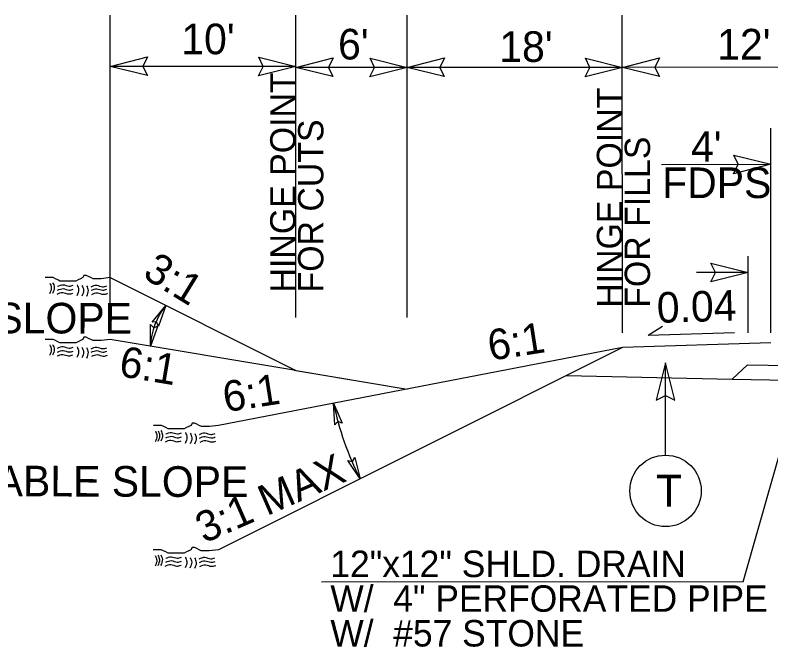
# Model space of a CAD drawing. Extents: x 2241081 to 2251104, y 658534 to 663427.
# Drawn here: x 2243852 to 2244055.6, y 661311.7 to 661481.9 of the extents above; entities that cross this region are included whole.
import ezdxf

# ---------------------------------------------------------------- set-up
doc = ezdxf.new("R2010")
doc.units = 0
for name, color, linetype in [('Old_Level_1', 7, 'Continuous'), ('Old_Level_2', 7, 'Continuous'), ('Old_Level_3', 7, 'Continuous'), ('Prop Dimension', 7, 'Continuous'), ('Prop Dimension Text', 7, 'Continuous'), ('Prop PHM Text', 7, 'Continuous'), ('Typical Arrow Superelevation CELL', 7, 'Continuous'), ('Typical Berm Information CELL', 7, 'Continuous'), ('Typical Hinge Slope Interstate CELL', 7, 'Continuous'), ('Typical ID Circle CELL', 7, 'Continuous'), ('Typical Terminator CELL', 7, 'Continuous'), ('Typical Text ID Circle CELL', 7, 'Continuous')]:
    doc.layers.add(name, color=color, linetype=linetype)

# ---------------------------------------------------------------- blocks, each defined once
blk = doc.blocks.new('TERMINATOR')
at = {"layer": 'Typical Terminator CELL'}
blk.add_lwpolyline([(-0.4687, 0.0807), (0, 0), (-0.4713, -0.0833), (-0.4114, 0)], close=True, dxfattribs=at)

msp = doc.modelspace()

# ---------------------------------------------------------------- linework, layer by layer
at = {"layer": 'Old_Level_1'}
for p, q in [((2243877.64, 661411.14), (2243927.64, 661386.14)), ((2243927.64, 661386.14), (2243877.64, 661394.48)), ((2244015.65, 661392.31), (2243906.82, 661371.36)), ((2243927.64, 661386.14), (2243949.64, 661382.48))]:
    msp.add_line(p, q, dxfattribs=at)
for points in [[(2243877.64, 661411.14), (2243875.17, 661410.84), (2243874.56, 661410.84), (2243873.63, 661410.84), (2243873.01, 661410.84), (2243872.4, 661411.15), (2243871.78, 661411.45), (2243871.17, 661411.76), (2243870.55, 661411.76), (2243870.24, 661411.15), (2243869.62, 661410.84), (2243869.01, 661410.53), (2243868.39, 661410.22), (2243867.78, 661410.22), (2243867.16, 661410.22), (2243866.54, 661410.22), (2243865.93, 661410.22), (2243865.31, 661410.22), (2243864.7, 661410.22), (2243864.08, 661410.22), (2243863.46, 661410.53), (2243862.85, 661410.84), (2243862.23, 661411.15), (2243861.31, 661411.15), (2243860.69, 661411.15), (2243860.07, 661411.15)], [(2243877.64, 661394.48), (2243875.17, 661394.17), (2243874.56, 661394.17), (2243873.63, 661394.17), (2243873.01, 661394.17), (2243872.4, 661394.48), (2243871.78, 661394.79), (2243871.17, 661395.1), (2243870.55, 661395.1), (2243870.24, 661394.48), (2243869.62, 661394.17), (2243869.01, 661393.86), (2243868.39, 661393.56), (2243867.78, 661393.56), (2243867.16, 661393.56), (2243866.54, 661393.56), (2243865.93, 661393.56), (2243865.31, 661393.56), (2243864.7, 661393.56), (2243864.08, 661393.56), (2243863.46, 661393.86), (2243862.85, 661394.17), (2243862.23, 661394.48), (2243861.31, 661394.48), (2243860.69, 661394.48), (2243860.07, 661394.48)], [(2243906.82, 661371.36), (2243904.35, 661371.06), (2243903.73, 661371.06), (2243902.81, 661371.06), (2243902.19, 661371.06), (2243901.58, 661371.36), (2243900.96, 661371.67), (2243900.34, 661371.98), (2243899.73, 661371.98), (2243899.42, 661371.36), (2243898.8, 661371.06), (2243898.19, 661370.75), (2243897.57, 661370.44), (2243896.95, 661370.44), (2243896.34, 661370.44), (2243895.72, 661370.44), (2243895.11, 661370.44), (2243894.49, 661370.44), (2243893.87, 661370.44), (2243893.26, 661370.44), (2243892.64, 661370.75), (2243892.03, 661371.06), (2243891.41, 661371.36), (2243890.48, 661371.36), (2243889.87, 661371.36), (2243889.25, 661371.36)], [(2243906.77, 661337.87), (2243904.31, 661337.57), (2243903.69, 661337.57), (2243902.77, 661337.57), (2243902.15, 661337.57), (2243901.54, 661337.87), (2243900.92, 661338.18), (2243900.3, 661338.49), (2243899.69, 661338.49), (2243899.38, 661337.87), (2243898.76, 661337.57), (2243898.15, 661337.26), (2243897.53, 661336.95), (2243896.91, 661336.95), (2243896.3, 661336.95), (2243895.68, 661336.95), (2243895.07, 661336.95), (2243894.45, 661336.95), (2243893.83, 661336.95), (2243893.22, 661336.95), (2243892.6, 661337.26), (2243891.98, 661337.57), (2243891.37, 661337.87), (2243890.44, 661337.87), (2243889.83, 661337.87), (2243889.21, 661337.87)]]:
    msp.add_lwpolyline(points, dxfattribs=at)
for points in [[(2243861.33, 661409.7), (2243861.75, 661408.45), (2243861.29, 661406.81)], [(2243861.33, 661409.7), (2243861.75, 661408.45), (2243861.29, 661406.81)], [(2243862.11, 661409.78), (2243862.53, 661408.54), (2243862.08, 661406.89)], [(2243862.11, 661409.78), (2243862.53, 661408.54), (2243862.08, 661406.89)], [(2243863.44, 661408.81), (2243864.93, 661409.24), (2243866.53, 661408.84), (2243867.67, 661409.1)], [(2243863.44, 661408.81), (2243864.93, 661409.24), (2243866.53, 661408.84), (2243867.67, 661409.1)], [(2243868.69, 661409.17), (2243869.11, 661407.93), (2243868.66, 661406.28)], [(2243868.69, 661409.17), (2243869.11, 661407.93), (2243868.66, 661406.28)], [(2243870.01, 661409.07), (2243870.43, 661407.82), (2243869.98, 661406.17)], [(2243870.01, 661409.07), (2243870.43, 661407.82), (2243869.98, 661406.17)], [(2243872.46, 661408.67), (2243873.97, 661409.1), (2243875.55, 661408.69), (2243876.7, 661408.95)], [(2243872.46, 661408.67), (2243873.97, 661409.1), (2243875.55, 661408.69), (2243876.7, 661408.95)], [(2243863.31, 661406.71), (2243864.81, 661407.13), (2243866.41, 661406.74), (2243867.55, 661406.99)], [(2243863.31, 661406.71), (2243864.81, 661407.13), (2243866.41, 661406.74), (2243867.55, 661406.99)], [(2243863.43, 661407.77), (2243864.93, 661408.19), (2243866.52, 661407.79), (2243867.66, 661408.04)], [(2243863.43, 661407.77), (2243864.93, 661408.19), (2243866.52, 661407.79), (2243867.66, 661408.04)], [(2243871.22, 661408.96), (2243871.64, 661407.71), (2243871.19, 661406.07)], [(2243871.22, 661408.96), (2243871.64, 661407.71), (2243871.19, 661406.07)], [(2243872.5, 661407.73), (2243874.01, 661408.16), (2243875.59, 661407.75), (2243876.74, 661408.01)], [(2243872.5, 661407.73), (2243874.01, 661408.16), (2243875.59, 661407.75), (2243876.74, 661408.01)], [(2243872.66, 661406.63), (2243874.16, 661407.06), (2243875.75, 661406.66), (2243876.9, 661406.92)], [(2243872.66, 661406.63), (2243874.16, 661407.06), (2243875.75, 661406.66), (2243876.9, 661406.92)], [(2243861.33, 661393.03), (2243861.75, 661391.79), (2243861.29, 661390.14)], [(2243861.33, 661393.03), (2243861.75, 661391.79), (2243861.29, 661390.14)], [(2243862.11, 661393.12), (2243862.53, 661391.87), (2243862.08, 661390.23)], [(2243862.11, 661393.12), (2243862.53, 661391.87), (2243862.08, 661390.23)], [(2243863.43, 661391.1), (2243864.93, 661391.53), (2243866.52, 661391.12), (2243867.66, 661391.38)], [(2243863.43, 661391.1), (2243864.93, 661391.53), (2243866.52, 661391.12), (2243867.66, 661391.38)], [(2243863.44, 661392.15), (2243864.93, 661392.58), (2243866.53, 661392.17), (2243867.67, 661392.43)], [(2243863.44, 661392.15), (2243864.93, 661392.58), (2243866.53, 661392.17), (2243867.67, 661392.43)], [(2243868.69, 661392.5), (2243869.11, 661391.26), (2243868.66, 661389.61)], [(2243868.69, 661392.5), (2243869.11, 661391.26), (2243868.66, 661389.61)], [(2243870.01, 661392.4), (2243870.43, 661391.16), (2243869.98, 661389.51)], [(2243870.01, 661392.4), (2243870.43, 661391.16), (2243869.98, 661389.51)], [(2243871.22, 661392.29), (2243871.64, 661391.05), (2243871.19, 661389.4)], [(2243871.22, 661392.29), (2243871.64, 661391.05), (2243871.19, 661389.4)], [(2243872.46, 661392.01), (2243873.97, 661392.43), (2243875.55, 661392.03), (2243876.7, 661392.28)], [(2243872.46, 661392.01), (2243873.97, 661392.43), (2243875.55, 661392.03), (2243876.7, 661392.28)], [(2243872.5, 661391.06), (2243874.01, 661391.49), (2243875.59, 661391.08), (2243876.74, 661391.34)], [(2243872.5, 661391.06), (2243874.01, 661391.49), (2243875.59, 661391.08), (2243876.74, 661391.34)], [(2243863.31, 661390.04), (2243864.81, 661390.47), (2243866.41, 661390.07), (2243867.55, 661390.33)], [(2243863.31, 661390.04), (2243864.81, 661390.47), (2243866.41, 661390.07), (2243867.55, 661390.33)], [(2243872.66, 661389.97), (2243874.16, 661390.4), (2243875.75, 661389.99), (2243876.9, 661390.25)], [(2243872.66, 661389.97), (2243874.16, 661390.4), (2243875.75, 661389.99), (2243876.9, 661390.25)]]:
    msp.add_spline(points, degree=3, dxfattribs=at)
at = {"layer": 'Old_Level_2'}
for p, q in [((2244055.65, 661393.61), (2244015.65, 661392.31)), ((2244049.3, 661387.7), (2244045.15, 661383.83)), ((2244049.3, 661387.7), (2244075.64, 661387.13)), ((2244000.6, 661384.78), (2244045.15, 661383.83)), ((2244045.15, 661383.83), (2244075.64, 661383.18))]:
    msp.add_line(p, q, dxfattribs=at)
for points in [[(2243889.78, 661369.78), (2243890.2, 661368.54), (2243889.74, 661366.89)], [(2243889.78, 661369.78), (2243890.2, 661368.54), (2243889.74, 661366.89)], [(2243890.51, 661369.92), (2243890.93, 661368.67), (2243890.47, 661367.02)], [(2243890.51, 661369.92), (2243890.93, 661368.67), (2243890.47, 661367.02)], [(2243891.28, 661370), (2243891.71, 661368.76), (2243891.26, 661367.11)], [(2243891.28, 661370), (2243891.71, 661368.76), (2243891.26, 661367.11)], [(2243892.61, 661369.03), (2243894.11, 661369.46), (2243895.71, 661369.06), (2243896.85, 661369.32)], [(2243892.61, 661369.03), (2243894.11, 661369.46), (2243895.71, 661369.06), (2243896.85, 661369.32)], [(2243892.61, 661367.98), (2243894.11, 661368.41), (2243895.7, 661368), (2243896.84, 661368.26)], [(2243892.61, 661367.98), (2243894.11, 661368.41), (2243895.7, 661368), (2243896.84, 661368.26)], [(2243897.87, 661369.39), (2243898.29, 661368.15), (2243897.84, 661366.5)], [(2243897.87, 661369.39), (2243898.29, 661368.15), (2243897.84, 661366.5)], [(2243899.18, 661369.28), (2243899.61, 661368.04), (2243899.16, 661366.39)], [(2243899.18, 661369.28), (2243899.61, 661368.04), (2243899.16, 661366.39)], [(2243900.4, 661369.18), (2243900.82, 661367.93), (2243900.36, 661366.29)], [(2243900.4, 661369.18), (2243900.82, 661367.93), (2243900.36, 661366.29)], [(2243901.64, 661368.89), (2243903.15, 661369.32), (2243904.73, 661368.91), (2243905.88, 661369.17)], [(2243901.64, 661368.89), (2243903.15, 661369.32), (2243904.73, 661368.91), (2243905.88, 661369.17)], [(2243901.68, 661367.94), (2243903.19, 661368.38), (2243904.77, 661367.97), (2243905.92, 661368.23)], [(2243901.68, 661367.94), (2243903.19, 661368.38), (2243904.77, 661367.97), (2243905.92, 661368.23)], [(2243892.49, 661366.93), (2243893.99, 661367.35), (2243895.59, 661366.96), (2243896.73, 661367.21)], [(2243892.49, 661366.93), (2243893.99, 661367.35), (2243895.59, 661366.96), (2243896.73, 661367.21)], [(2243901.84, 661366.85), (2243903.34, 661367.28), (2243904.93, 661366.88), (2243906.08, 661367.14)], [(2243889.74, 661336.28), (2243890.16, 661335.04), (2243889.7, 661333.4)], [(2243889.74, 661336.28), (2243890.16, 661335.04), (2243889.7, 661333.4)], [(2243890.47, 661336.43), (2243890.88, 661335.18), (2243890.43, 661333.53)], [(2243890.47, 661336.43), (2243890.88, 661335.18), (2243890.43, 661333.53)], [(2243891.24, 661336.51), (2243891.67, 661335.26), (2243891.21, 661333.62)], [(2243891.24, 661336.51), (2243891.67, 661335.26), (2243891.21, 661333.62)], [(2243892.57, 661335.54), (2243894.07, 661335.97), (2243895.67, 661335.57), (2243896.81, 661335.82)], [(2243892.57, 661335.54), (2243894.07, 661335.97), (2243895.67, 661335.57), (2243896.81, 661335.82)], [(2243897.83, 661335.89), (2243898.25, 661334.65), (2243897.8, 661333.01)], [(2243897.83, 661335.89), (2243898.25, 661334.65), (2243897.8, 661333.01)], [(2243899.14, 661335.79), (2243899.57, 661334.55), (2243899.11, 661332.9)], [(2243899.14, 661335.79), (2243899.57, 661334.55), (2243899.11, 661332.9)], [(2243900.36, 661335.68), (2243900.78, 661334.44), (2243900.32, 661332.8)], [(2243900.36, 661335.68), (2243900.78, 661334.44), (2243900.32, 661332.8)], [(2243901.6, 661335.4), (2243903.11, 661335.83), (2243904.69, 661335.42), (2243905.84, 661335.67)], [(2243901.6, 661335.4), (2243903.11, 661335.83), (2243904.69, 661335.42), (2243905.84, 661335.67)], [(2243892.45, 661333.44), (2243893.95, 661333.86), (2243895.55, 661333.46), (2243896.69, 661333.72)], [(2243892.45, 661333.44), (2243893.95, 661333.86), (2243895.55, 661333.46), (2243896.69, 661333.72)], [(2243892.56, 661334.49), (2243894.07, 661334.92), (2243895.66, 661334.51), (2243896.8, 661334.77)], [(2243892.56, 661334.49), (2243894.07, 661334.92), (2243895.66, 661334.51), (2243896.8, 661334.77)], [(2243901.64, 661334.45), (2243903.15, 661334.89), (2243904.73, 661334.48), (2243905.88, 661334.73)], [(2243901.64, 661334.45), (2243903.15, 661334.89), (2243904.73, 661334.48), (2243905.88, 661334.73)], [(2243901.79, 661333.36), (2243903.3, 661333.79), (2243904.89, 661333.39), (2243906.03, 661333.64)]]:
    msp.add_spline(points, degree=3, dxfattribs=at)
at = {"layer": 'Prop Dimension'}
for centre, radius, start, end in [((2243907.58, 661391.82), 19.12, 141.6676, 177.4305), ((2244017.16, 661393.77), 81.05, 191.6788, 206.9901)]:
    msp.add_arc(centre, radius, start, end, dxfattribs=at)
at = {"layer": 'Prop Dimension Text'}
for p, q in [((2243877.63, 661400.38), (2243877.63, 661481.85)), ((2243927.63, 661400.38), (2243927.63, 661481.85)), ((2243957.63, 661400.38), (2243957.63, 661481.85)), ((2244015.64, 661396.26), (2244015.59, 661481.85)), ((2243877.63, 661468.17), (2243877.63, 661468.17)), ((2243927.63, 661468.04), (2243877.63, 661468.04)), ((2243927.63, 661468.17), (2243927.63, 661468.17)), ((2243957.63, 661467.78), (2243927.63, 661467.78)), ((2244015.65, 661467.78), (2243957.63, 661467.78)), ((2244075.6, 661467.82), (2244015.6, 661467.78)), ((2244055.64, 661396.29), (2244055.61, 661451.37)), ((2244026.17, 661441.66), (2244055.62, 661441.68)), ((2244049.46, 661396.29), (2244049.46, 661416.95)), ((2244049.46, 661412.56), (2244035.59, 661412.55)), ((2244048.2, 661329.21), (2244060.85, 661373.9)), ((2244048.2, 661329.21), (2243934.53, 661329.14))]:
    msp.add_line(p, q, dxfattribs=at)
at = {"layer": 'Typical Arrow Superelevation CELL'}
for q in [(2244026.44, 661398.06), (2244045.85, 661396.35)]:
    msp.add_line((2244022.55, 661395.65), q, dxfattribs=at)
at = {"layer": 'Typical Hinge Slope Interstate CELL'}
for p, q in [((2244015.65, 661392.31), (2243906.77, 661337.87)), ((2243927.14, 661386.23), (2243957.64, 661381.14))]:
    msp.add_line(p, q, dxfattribs=at)
at = {"layer": 'Typical ID Circle CELL'}
msp.add_line((2244027.24, 661363.31), (2244027.24, 661388.17), dxfattribs=at)
msp.add_circle((2244027.24, 661353.7), 9.62, dxfattribs=at)
at = {"layer": 'Typical Terminator CELL'}
for points in [[(2243888.92, 661399.11), (2243892.58, 661403.67), (2243890.67, 661398.1), (2243890.13, 661399.24)], [(2243890.47, 661398.17), (2243888.48, 661392.67), (2243888.49, 661398.56), (2243889.37, 661397.66)], [(2243938.18, 661371.52), (2243937.78, 661377.36), (2243940.15, 661371.96), (2243938.98, 661372.44)], [(2243943.52, 661362.66), (2243944.93, 661356.98), (2243941.66, 661361.88), (2243942.9, 661361.62)]]:
    msp.add_lwpolyline(points, close=True, dxfattribs=at)

# ---------------------------------------------------------------- block references
for p, xscale, yscale, rotation in [((2243877.63, 661468.04), 21.314641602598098, 30.593161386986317, -179.96511250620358), ((2243927.63, 661468.04), 21.314641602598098, 30.593161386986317, 0.03488749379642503), ((2243927.63, 661467.78), 21.314641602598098, 30.593161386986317, -179.96511250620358), ((2243957.63, 661467.78), 21.314641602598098, 30.593161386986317, 0.03488749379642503), ((2243957.63, 661467.78), 21.314641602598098, 30.593161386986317, -179.96511250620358), ((2244015.65, 661467.78), 21.314641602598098, 30.593161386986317, 0.03488749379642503), ((2244015.6, 661467.78), 21.314641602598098, 30.593161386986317, -179.96511250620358), ((2244055.62, 661441.68), 21.314641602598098, 30.593161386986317, 0.03488749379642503), ((2244049.46, 661412.56), 21.314641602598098, 30.593161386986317, 0.03488749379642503), ((2244027.24, 661388.17), 21.3146416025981, -30.593161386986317, 89.9999349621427)]:
    msp.add_blockref('TERMINATOR', p, dxfattribs=dict(at, xscale=xscale, yscale=yscale, rotation=rotation))

# ---------------------------------------------------------------- texts
at = {"layer": 'Old_Level_3'}
for s, p in [('12"x12" SHLD. DRAIN', (2243936.93, 661330.49)), ('W/  4" PERFORATED PIPE', (2243936.93, 661321.14)), ('W/  #57 STONE', (2243936.93, 661311.79))]:
    msp.add_text(s, height=7.1311, rotation=359.9999, dxfattribs=at).set_placement(p)
at = {"layer": 'Prop Dimension Text'}
for s, rotation, p in [("10'", 359.9999, (2243896.77, 661471.31)), ("6'", 359.9999, (2243939, 661469.91)), ("12'", 0.0349, (2244041.16, 661469.89)), ("18'", 359.9999, (2243982.44, 661469.25)), ("4'", 0.0349, (2244034.1, 661442.34)), ('FDPS', 0.0349, (2244026.34, 661432.56)), ('6:1', 8.8656, (2243980.02, 661388.74)), ('6:1', 8.8656, (2243908.64, 661374.87))]:
    msp.add_text(s, height=8.25, rotation=rotation, dxfattribs=at).set_placement(p)
at = {"layer": 'Prop PHM Text'}
for s, height, p in [('HINGE POINT', 6.8193, (2243927.54, 661407.15)), ('HINGE POINT', 6.8193, (2244015.55, 661403.03)), ('FOR CUTS', 6.819, (2243935.05, 661407.15)), ('FOR FILLS', 6.819, (2244023.06, 661403.03))]:
    msp.add_text(s, height=height, rotation=89.9999, dxfattribs=at).set_placement(p)
at = {"layer": 'Typical Berm Information CELL'}
msp.add_text('0.04', height=8.25, rotation=1.7135, dxfattribs=at).set_placement((2244025.01, 661398.94))
at = {"layer": 'Typical Hinge Slope Interstate CELL'}
for s, rotation, p in [('3:1', 328.4414, (2243886.04, 661411.38)), ('VARIABLE SLOPE', 359.8157, (2243789.65, 661396.35)), ('6:1', 350.5376, (2243879.7, 661384.67)), ('3:1 MAX', 23.6411, (2243902.94, 661339.49)), ('VARIABLE SLOPE', 359.8157, (2243821, 661352.34))]:
    msp.add_text(s, height=8.25, rotation=rotation, dxfattribs=at).set_placement(p)
at = {"layer": 'Typical Text ID Circle CELL'}
msp.add_text('T', height=8.61, rotation=359.9999, dxfattribs=at).set_placement((2244024.68, 661349.46))

doc.saveas('drawing.dxf')
